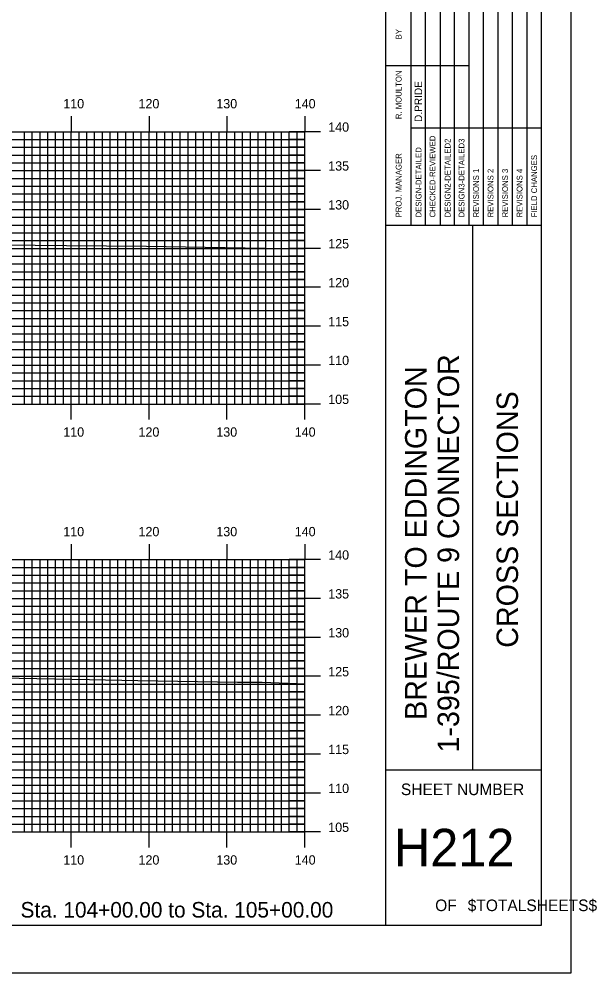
# Model space of a CAD drawing. Extents: x 1767694 to 1768037, y 442591 to 442811.
# Drawn here: x 1767962.8 to 1768036.9, y 442590.5 to 442713.1 of the extents above; entities that cross this region are included whole.
import ezdxf

# ---------------------------------------------------------------- set-up
doc = ezdxf.new("R2010")
doc.units = 0
for name, color, linetype in [('BORDER', 7, 'Continuous'), ('H_V ANNOTATION', 7, 'Continuous'), ('MAJOR', 7, 'Continuous'), ('MINOR', 7, 'Continuous'), ('PLOT BOUNDARY', 7, 'Continuous'), ('S_Roadway_Centerline', 7, 'Continuous')]:
    doc.layers.add(name, color=color, linetype=linetype)

msp = doc.modelspace()

# ---------------------------------------------------------------- linework, layer by layer
at = {"layer": 'BORDER'}
for p, q in [((1768009.85, 442596.67), (1768009.85, 442806.67)), ((1768009.85, 442686.67), (1768029.85, 442686.67)), ((1768021.03, 442616.67), (1768021.03, 442686.67)), ((1768009.85, 442616.67), (1768029.85, 442616.67))]:
    msp.add_line(p, q, dxfattribs=at)
msp.add_lwpolyline([(1767709.85, 442596.67), (1768029.85, 442596.67), (1768029.85, 442806.67), (1767709.85, 442806.67)], close=True, dxfattribs=at)
for points in [[(1768014.94, 442686.68), (1768014.94, 442721.67)], [(1768016.81, 442721.67), (1768016.81, 442686.68)], [(1768018.67, 442686.68), (1768018.67, 442721.67)], [(1768020.53, 442686.68), (1768020.53, 442721.67)], [(1768022.4, 442686.68), (1768022.4, 442721.67)], [(1768024.26, 442686.68), (1768024.26, 442721.67)], [(1768026.12, 442686.68), (1768026.12, 442721.67)], [(1768027.99, 442686.68), (1768027.99, 442721.67)], [(1768013.08, 442686.68), (1768013.08, 442720.26)], [(1768009.85, 442707.17), (1768013.08, 442707.17)], [(1768013.08, 442707.17), (1768020.53, 442707.17)], [(1768013.08, 442699.17), (1768029.85, 442699.17)]]:
    msp.add_lwpolyline(points, dxfattribs=at)
at = {"layer": 'MAJOR'}
for p, q in [((1767969.45, 442700.67), (1767969.45, 442698.67)), ((1767979.45, 442700.67), (1767979.45, 442698.67)), ((1767989.45, 442700.67), (1767989.45, 442698.67)), ((1767999.45, 442700.67), (1767999.45, 442698.67)), ((1767719.45, 442698.67), (1767999.45, 442698.67)), ((1767719.45, 442698.67), (1767999.45, 442698.67)), ((1767969.45, 442663.67), (1767969.45, 442698.67)), ((1767979.45, 442663.67), (1767979.45, 442698.67)), ((1767989.45, 442663.67), (1767989.45, 442698.67)), ((1768001.45, 442698.67), (1767997.45, 442698.67)), ((1767999.45, 442663.67), (1767999.45, 442698.67)), ((1767999.45, 442663.67), (1767999.45, 442698.67)), ((1767719.45, 442693.67), (1767999.45, 442693.67)), ((1768001.45, 442693.67), (1767997.45, 442693.67)), ((1767719.45, 442688.67), (1767999.45, 442688.67)), ((1768001.45, 442688.67), (1767997.45, 442688.67)), ((1767719.45, 442683.67), (1767999.45, 442683.67)), ((1768001.45, 442683.67), (1767997.45, 442683.67)), ((1767719.45, 442678.67), (1767999.45, 442678.67)), ((1768001.45, 442678.67), (1767997.45, 442678.67)), ((1767719.45, 442673.67), (1767999.45, 442673.67)), ((1768001.45, 442673.67), (1767997.45, 442673.67)), ((1767719.45, 442668.67), (1767999.45, 442668.67)), ((1768001.45, 442668.67), (1767997.45, 442668.67)), ((1767719.45, 442663.67), (1767999.45, 442663.67)), ((1767719.45, 442663.67), (1767999.45, 442663.67)), ((1767969.45, 442661.66), (1767969.45, 442663.67)), ((1767979.45, 442661.66), (1767979.45, 442663.67)), ((1767989.45, 442661.66), (1767989.45, 442663.67)), ((1768001.45, 442663.67), (1767997.45, 442663.67)), ((1767999.45, 442661.66), (1767999.45, 442663.67)), ((1767969.45, 442645.67), (1767969.45, 442643.67)), ((1767979.45, 442645.67), (1767979.45, 442643.67)), ((1767989.45, 442645.67), (1767989.45, 442643.67)), ((1767999.45, 442645.67), (1767999.45, 442643.67)), ((1767719.45, 442643.67), (1767999.45, 442643.67)), ((1767719.45, 442643.67), (1767999.45, 442643.67)), ((1767969.45, 442608.67), (1767969.45, 442643.67)), ((1767979.45, 442608.67), (1767979.45, 442643.67)), ((1767989.45, 442608.67), (1767989.45, 442643.67)), ((1768001.45, 442643.67), (1767997.45, 442643.67)), ((1767999.45, 442608.67), (1767999.45, 442643.67)), ((1767999.45, 442608.67), (1767999.45, 442643.67)), ((1767719.45, 442638.67), (1767999.45, 442638.67)), ((1768001.45, 442638.67), (1767997.45, 442638.67)), ((1767719.45, 442633.67), (1767999.45, 442633.67)), ((1768001.45, 442633.67), (1767997.45, 442633.67)), ((1767719.45, 442628.67), (1767999.45, 442628.67)), ((1768001.45, 442628.67), (1767997.45, 442628.67)), ((1767719.45, 442623.67), (1767999.45, 442623.67)), ((1768001.45, 442623.67), (1767997.45, 442623.67)), ((1767719.45, 442618.67), (1767999.45, 442618.67)), ((1768001.45, 442618.67), (1767997.45, 442618.67)), ((1767719.45, 442613.67), (1767999.45, 442613.67)), ((1768001.45, 442613.67), (1767997.45, 442613.67)), ((1767719.45, 442608.67), (1767999.45, 442608.67)), ((1767719.45, 442608.67), (1767999.45, 442608.67)), ((1767969.45, 442606.66), (1767969.45, 442608.67)), ((1767979.45, 442606.66), (1767979.45, 442608.67)), ((1767989.45, 442606.66), (1767989.45, 442608.67)), ((1768001.45, 442608.67), (1767997.45, 442608.67)), ((1767999.45, 442606.66), (1767999.45, 442608.67))]:
    msp.add_line(p, q, dxfattribs=at)
at = {"layer": 'MINOR'}
for p, q in [((1767963.45, 442663.67), (1767963.45, 442698.67)), ((1767964.45, 442663.67), (1767964.45, 442698.67)), ((1767965.45, 442663.67), (1767965.45, 442698.67)), ((1767966.45, 442663.67), (1767966.45, 442698.67)), ((1767967.45, 442663.67), (1767967.45, 442698.67)), ((1767968.45, 442663.67), (1767968.45, 442698.67)), ((1767970.45, 442663.67), (1767970.45, 442698.67)), ((1767971.45, 442663.67), (1767971.45, 442698.67)), ((1767972.45, 442663.67), (1767972.45, 442698.67)), ((1767973.45, 442663.67), (1767973.45, 442698.67)), ((1767974.45, 442663.67), (1767974.45, 442698.67)), ((1767975.45, 442663.67), (1767975.45, 442698.67)), ((1767976.45, 442663.67), (1767976.45, 442698.67)), ((1767977.45, 442663.67), (1767977.45, 442698.67)), ((1767978.45, 442663.67), (1767978.45, 442698.67)), ((1767980.45, 442663.67), (1767980.45, 442698.67)), ((1767981.45, 442663.67), (1767981.45, 442698.67)), ((1767982.45, 442663.67), (1767982.45, 442698.67)), ((1767983.45, 442663.67), (1767983.45, 442698.67)), ((1767984.45, 442663.67), (1767984.45, 442698.67)), ((1767985.45, 442663.67), (1767985.45, 442698.67)), ((1767986.45, 442663.67), (1767986.45, 442698.67)), ((1767987.45, 442663.67), (1767987.45, 442698.67)), ((1767988.45, 442663.67), (1767988.45, 442698.67)), ((1767990.45, 442663.67), (1767990.45, 442698.67)), ((1767991.45, 442663.67), (1767991.45, 442698.67)), ((1767992.45, 442663.67), (1767992.45, 442698.67)), ((1767993.45, 442663.67), (1767993.45, 442698.67)), ((1767994.45, 442663.67), (1767994.45, 442698.67)), ((1767995.45, 442663.67), (1767995.45, 442698.67)), ((1767996.45, 442663.67), (1767996.45, 442698.67)), ((1767997.45, 442663.67), (1767997.45, 442698.67)), ((1767998.45, 442663.67), (1767998.45, 442698.67)), ((1767719.45, 442697.67), (1767999.45, 442697.67)), ((1767719.45, 442696.67), (1767999.45, 442696.67)), ((1767999.45, 442697.67), (1767997.45, 442697.67)), ((1767999.45, 442696.67), (1767997.45, 442696.67)), ((1767719.45, 442695.67), (1767999.45, 442695.67)), ((1767999.45, 442695.67), (1767997.45, 442695.67)), ((1767719.45, 442694.67), (1767999.45, 442694.67)), ((1767999.45, 442694.67), (1767997.45, 442694.67)), ((1767719.45, 442692.67), (1767999.45, 442692.67)), ((1767999.45, 442692.67), (1767997.45, 442692.67)), ((1767719.45, 442691.67), (1767999.45, 442691.67)), ((1767719.45, 442690.67), (1767999.45, 442690.67)), ((1767999.45, 442691.67), (1767997.45, 442691.67)), ((1767999.45, 442690.67), (1767997.45, 442690.67)), ((1767719.45, 442689.67), (1767999.45, 442689.67)), ((1767999.45, 442689.67), (1767997.45, 442689.67)), ((1767719.45, 442687.67), (1767999.45, 442687.67)), ((1767999.45, 442687.67), (1767997.45, 442687.67)), ((1767719.45, 442686.67), (1767999.45, 442686.67)), ((1767719.45, 442685.67), (1767999.45, 442685.67)), ((1767999.45, 442686.67), (1767997.45, 442686.67)), ((1767999.45, 442685.67), (1767997.45, 442685.67)), ((1767719.45, 442684.67), (1767999.45, 442684.67)), ((1767999.45, 442684.67), (1767997.45, 442684.67)), ((1767719.45, 442682.67), (1767999.45, 442682.67)), ((1767999.45, 442682.67), (1767997.45, 442682.67)), ((1767719.45, 442681.67), (1767999.45, 442681.67)), ((1767999.45, 442681.67), (1767997.45, 442681.67)), ((1767719.45, 442680.67), (1767999.45, 442680.67)), ((1767719.45, 442679.67), (1767999.45, 442679.67)), ((1767999.45, 442680.67), (1767997.45, 442680.67)), ((1767999.45, 442679.67), (1767997.45, 442679.67)), ((1767719.45, 442677.67), (1767999.45, 442677.67)), ((1767999.45, 442677.67), (1767997.45, 442677.67)), ((1767719.45, 442676.67), (1767999.45, 442676.67)), ((1767999.45, 442676.67), (1767997.45, 442676.67)), ((1767719.45, 442675.67), (1767999.45, 442675.67)), ((1767719.45, 442674.67), (1767999.45, 442674.67)), ((1767999.45, 442675.67), (1767997.45, 442675.67)), ((1767999.45, 442674.67), (1767997.45, 442674.67)), ((1767719.45, 442672.67), (1767999.45, 442672.67)), ((1767999.45, 442672.67), (1767997.45, 442672.67)), ((1767719.45, 442671.67), (1767999.45, 442671.67)), ((1767999.45, 442671.67), (1767997.45, 442671.67)), ((1767719.45, 442670.67), (1767999.45, 442670.67)), ((1767719.45, 442669.67), (1767999.45, 442669.67)), ((1767999.45, 442670.67), (1767997.45, 442670.67)), ((1767999.45, 442669.67), (1767997.45, 442669.67)), ((1767719.45, 442667.67), (1767999.45, 442667.67)), ((1767999.45, 442667.67), (1767997.45, 442667.67)), ((1767719.45, 442666.67), (1767999.45, 442666.67)), ((1767999.45, 442666.67), (1767997.45, 442666.67)), ((1767719.45, 442665.67), (1767999.45, 442665.67)), ((1767999.45, 442665.67), (1767997.45, 442665.67)), ((1767719.45, 442664.67), (1767999.45, 442664.67)), ((1767999.45, 442664.67), (1767997.45, 442664.67)), ((1767963.45, 442608.67), (1767963.45, 442643.67)), ((1767964.45, 442608.67), (1767964.45, 442643.67)), ((1767965.45, 442608.67), (1767965.45, 442643.67)), ((1767966.45, 442608.67), (1767966.45, 442643.67)), ((1767967.45, 442608.67), (1767967.45, 442643.67)), ((1767968.45, 442608.67), (1767968.45, 442643.67)), ((1767970.45, 442608.67), (1767970.45, 442643.67)), ((1767971.45, 442608.67), (1767971.45, 442643.67)), ((1767972.45, 442608.67), (1767972.45, 442643.67)), ((1767973.45, 442608.67), (1767973.45, 442643.67)), ((1767974.45, 442608.67), (1767974.45, 442643.67)), ((1767975.45, 442608.67), (1767975.45, 442643.67)), ((1767976.45, 442608.67), (1767976.45, 442643.67)), ((1767977.45, 442608.67), (1767977.45, 442643.67)), ((1767978.45, 442608.67), (1767978.45, 442643.67)), ((1767980.45, 442608.67), (1767980.45, 442643.67)), ((1767981.45, 442608.67), (1767981.45, 442643.67)), ((1767982.45, 442608.67), (1767982.45, 442643.67)), ((1767983.45, 442608.67), (1767983.45, 442643.67)), ((1767984.45, 442608.67), (1767984.45, 442643.67)), ((1767985.45, 442608.67), (1767985.45, 442643.67)), ((1767986.45, 442608.67), (1767986.45, 442643.67)), ((1767987.45, 442608.67), (1767987.45, 442643.67)), ((1767988.45, 442608.67), (1767988.45, 442643.67)), ((1767990.45, 442608.67), (1767990.45, 442643.67)), ((1767991.45, 442608.67), (1767991.45, 442643.67)), ((1767992.45, 442608.67), (1767992.45, 442643.67)), ((1767993.45, 442608.67), (1767993.45, 442643.67)), ((1767994.45, 442608.67), (1767994.45, 442643.67)), ((1767995.45, 442608.67), (1767995.45, 442643.67)), ((1767996.45, 442608.67), (1767996.45, 442643.67)), ((1767997.45, 442608.67), (1767997.45, 442643.67)), ((1767998.45, 442608.67), (1767998.45, 442643.67)), ((1767719.45, 442642.67), (1767999.45, 442642.67)), ((1767719.45, 442641.67), (1767999.45, 442641.67)), ((1767999.45, 442642.67), (1767997.45, 442642.67)), ((1767999.45, 442641.67), (1767997.45, 442641.67)), ((1767719.45, 442640.67), (1767999.45, 442640.67)), ((1767999.45, 442640.67), (1767997.45, 442640.67)), ((1767719.45, 442639.67), (1767999.45, 442639.67)), ((1767999.45, 442639.67), (1767997.45, 442639.67)), ((1767719.45, 442637.67), (1767999.45, 442637.67)), ((1767719.45, 442636.67), (1767999.45, 442636.67)), ((1767999.45, 442637.67), (1767997.45, 442637.67)), ((1767999.45, 442636.67), (1767997.45, 442636.67)), ((1767719.45, 442635.67), (1767999.45, 442635.67)), ((1767999.45, 442635.67), (1767997.45, 442635.67)), ((1767719.45, 442634.67), (1767999.45, 442634.67)), ((1767999.45, 442634.67), (1767997.45, 442634.67)), ((1767719.45, 442632.67), (1767999.45, 442632.67)), ((1767719.45, 442631.67), (1767999.45, 442631.67)), ((1767999.45, 442632.67), (1767997.45, 442632.67)), ((1767999.45, 442631.67), (1767997.45, 442631.67)), ((1767719.45, 442630.67), (1767999.45, 442630.67)), ((1767999.45, 442630.67), (1767997.45, 442630.67)), ((1767719.45, 442629.67), (1767999.45, 442629.67)), ((1767999.45, 442629.67), (1767997.45, 442629.67)), ((1767719.45, 442627.67), (1767999.45, 442627.67)), ((1767999.45, 442627.67), (1767997.45, 442627.67)), ((1767719.45, 442626.67), (1767999.45, 442626.67)), ((1767719.45, 442625.67), (1767999.45, 442625.67)), ((1767999.45, 442626.67), (1767997.45, 442626.67)), ((1767999.45, 442625.67), (1767997.45, 442625.67)), ((1767719.45, 442624.67), (1767999.45, 442624.67)), ((1767999.45, 442624.67), (1767997.45, 442624.67)), ((1767719.45, 442622.67), (1767999.45, 442622.67)), ((1767999.45, 442622.67), (1767997.45, 442622.67)), ((1767719.45, 442621.67), (1767999.45, 442621.67)), ((1767719.45, 442620.67), (1767999.45, 442620.67)), ((1767999.45, 442621.67), (1767997.45, 442621.67)), ((1767999.45, 442620.67), (1767997.45, 442620.67)), ((1767719.45, 442619.67), (1767999.45, 442619.67)), ((1767999.45, 442619.67), (1767997.45, 442619.67)), ((1767719.45, 442617.67), (1767999.45, 442617.67)), ((1767999.45, 442617.67), (1767997.45, 442617.67)), ((1767719.45, 442616.67), (1767999.45, 442616.67)), ((1767999.45, 442616.67), (1767997.45, 442616.67)), ((1767719.45, 442615.67), (1767999.45, 442615.67)), ((1767719.45, 442614.67), (1767999.45, 442614.67)), ((1767999.45, 442615.67), (1767997.45, 442615.67)), ((1767999.45, 442614.67), (1767997.45, 442614.67)), ((1767719.45, 442612.67), (1767999.45, 442612.67)), ((1767999.45, 442612.67), (1767997.45, 442612.67)), ((1767719.45, 442611.67), (1767999.45, 442611.67)), ((1767999.45, 442611.67), (1767997.45, 442611.67)), ((1767719.45, 442610.67), (1767999.45, 442610.67)), ((1767719.45, 442609.67), (1767999.45, 442609.67)), ((1767999.45, 442610.67), (1767997.45, 442610.67)), ((1767999.45, 442609.67), (1767997.45, 442609.67))]:
    msp.add_line(p, q, dxfattribs=at)
at = {"layer": 'PLOT BOUNDARY'}
msp.add_lwpolyline([(1767693.66, 442590.55), (1768033.66, 442590.55), (1768033.66, 442810.55), (1767693.66, 442810.55)], close=True, dxfattribs=at)
at = {"layer": 'S_Roadway_Centerline'}
for points in [[(1767886.88, 442690.66), (1767891.9, 442690.55), (1767898.86, 442690.44), (1767903.21, 442690.12), (1767919.08, 442688.7), (1767922.1, 442688.44), (1767922.94, 442688.37), (1767924.29, 442688.06), (1767935.06, 442685.57), (1767941.89, 442685.1), (1767955.26, 442684.32), (1767960.79, 442684.13), (1767968.85, 442684.06), (1767979.13, 442683.94), (1767986.66, 442683.83), (1767999.45, 442683.63)], [(1767880.33, 442634.9), (1767894.58, 442634.55), (1767904.18, 442633.83), (1767911.9, 442633.23), (1767914.49, 442632.9), (1767926.83, 442631.21), (1767932.98, 442630.16), (1767946.05, 442629.35), (1767952.52, 442628.81), (1767955.89, 442628.55), (1767967.31, 442628.36), (1767971.79, 442628.27), (1767978, 442628.15), (1767990.79, 442627.93), (1767993.95, 442627.91), (1767999.45, 442627.7)]]:
    msp.add_lwpolyline(points, dxfattribs=at)

# ---------------------------------------------------------------- texts
at = {"layer": 'BORDER'}
for s, height, p in [('BY', 0.743, (1768011.86, 442710.54)), ('R. MOULTON', 0.745, (1768011.86, 442700.28)), ('D.PRIDE', 0.969, (1768014.5, 442699.92)), ('CHECKED-REVIEWED', 0.7455, (1768016.21, 442687.65)), ('DESIGN-DETAILED', 0.7455, (1768014.42, 442687.65)), ('DESIGN2-DETAILED2', 0.7455, (1768018.15, 442687.65)), ('DESIGN3-DETAILED3', 0.7455, (1768019.94, 442687.65)), ('PROJ. MANAGER', 0.7455, (1768011.86, 442687.65)), ('FIELD CHANGES', 0.7455, (1768029.26, 442687.65)), ('REVISIONS 1', 0.7455, (1768021.8, 442687.65)), ('REVISIONS 2', 0.7455, (1768023.66, 442687.65)), ('REVISIONS 3', 0.7455, (1768025.53, 442687.65)), ('REVISIONS 4', 0.7455, (1768027.39, 442687.65)), ('1-395/ROUTE 9 CONNECTOR', 2.7557, (1768019.25, 442618.87)), ('BREWER TO EDDINGTON', 2.7557, (1768015.07, 442623.07)), ('CROSS SECTIONS', 2.7557, (1768026.82, 442632.34))]:
    msp.add_text(s, height=height, rotation=90, dxfattribs=at).set_placement(p)
for s, height, p in [('SHEET NUMBER', 1.4905, (1768011.78, 442613.4)), ('H212', 4.839, (1768010.88, 442604.23)), ('OF', 1.491, (1768016.18, 442598.49)), ('$TOTALSHEETS$', 1.4905, (1768020.36, 442598.49))]:
    msp.add_text(s, height=height, dxfattribs=at).set_placement(p)
at = {"layer": 'H_V ANNOTATION'}
for s, height, p in [('110', 1.2, (1767968.43, 442701.67)), ('120', 1.2, (1767978.09, 442701.67)), ('130', 1.2, (1767988.08, 442701.67)), ('140', 1.2, (1767998.15, 442701.67)), ('140', 1.2, (1768002.45, 442698.67)), ('135', 1.2, (1768002.45, 442693.67)), ('130', 1.2, (1768002.45, 442688.67)), ('125', 1.2, (1768002.45, 442683.67)), ('120', 1.2, (1768002.45, 442678.67)), ('115', 1.2, (1768002.45, 442673.67)), ('110', 1.2, (1768002.45, 442668.67)), ('105', 1.2, (1768002.45, 442663.67)), ('110', 1.2, (1767968.43, 442659.47)), ('120', 1.2, (1767978.09, 442659.47)), ('130', 1.2, (1767988.08, 442659.47)), ('140', 1.2, (1767998.15, 442659.47)), ('110', 1.2, (1767968.43, 442646.67)), ('120', 1.2, (1767978.09, 442646.67)), ('130', 1.2, (1767988.08, 442646.67)), ('140', 1.2, (1767998.15, 442646.67)), ('140', 1.2, (1768002.45, 442643.67)), ('135', 1.2, (1768002.45, 442638.67)), ('130', 1.2, (1768002.45, 442633.67)), ('125', 1.2, (1768002.45, 442628.67)), ('120', 1.2, (1768002.45, 442623.67)), ('115', 1.2, (1768002.45, 442618.67)), ('110', 1.2, (1768002.45, 442613.67)), ('105', 1.2, (1768002.45, 442608.67)), ('110', 1.2, (1767968.43, 442604.47)), ('120', 1.2, (1767978.09, 442604.47)), ('130', 1.2, (1767988.08, 442604.47)), ('140', 1.2, (1767998.15, 442604.47)), ('Sta. 104+00.00 to Sta. 105+00.00', 2.0004, (1767962.94, 442597.66))]:
    msp.add_text(s, height=height, dxfattribs=at).set_placement(p)

doc.saveas('drawing.dxf')
